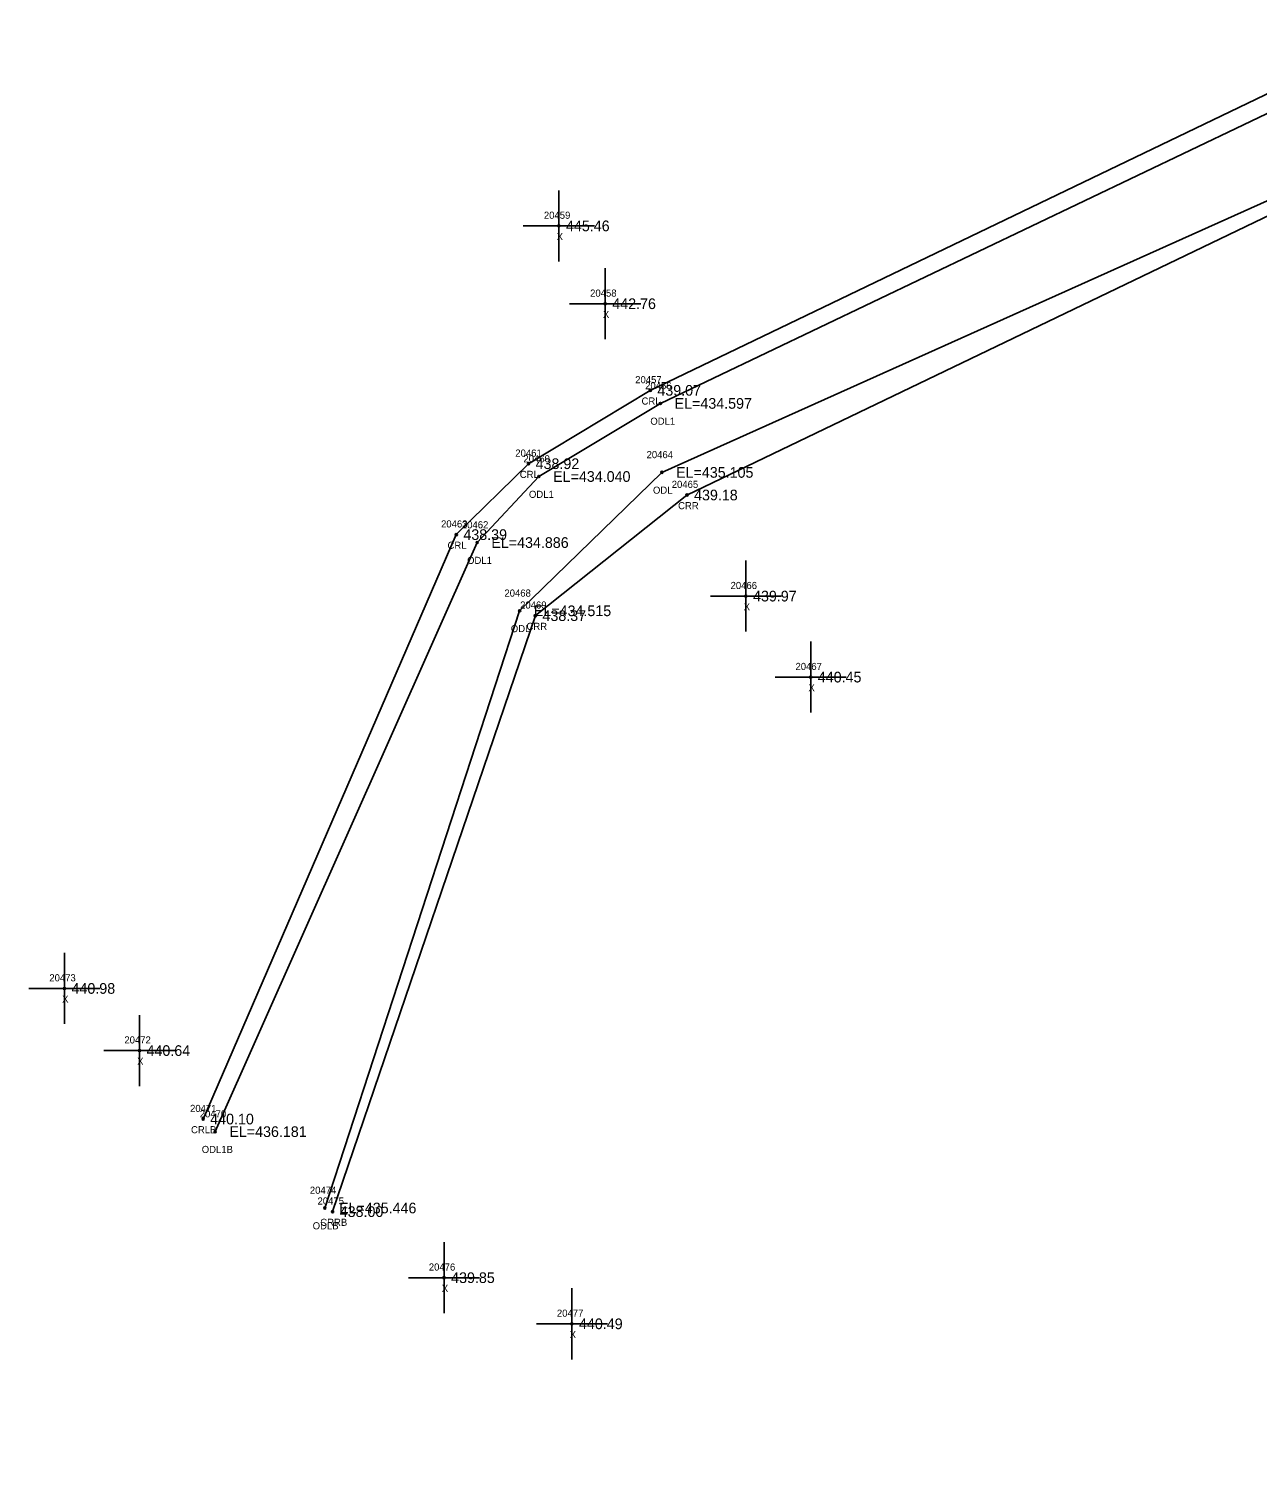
# Model space of a CAD drawing. Extents: x 1763022 to 1764007, y 824123 to 825394.
# Drawn here: x 1763021.6 to 1763194.4, y 824815.6 to 825018.5 of the extents above; entities that cross this region are included whole.
import ezdxf

# ---------------------------------------------------------------- set-up
doc = ezdxf.new("R2010")
doc.units = 0
for name, color, linetype in [('RD_EX_H2O', 7, 'Continuous'), ('RD_EX_H2O_txCode', 7, 'Continuous'), ('RD_EX_Misc', 7, 'Continuous'), ('RD_EX_Misc_txCode', 7, 'Continuous'), ('RD_EX_TX_H2O_ELEV', 7, 'Continuous'), ('RD_EX_TX_Misc_ELEV', 7, 'Continuous'), ('RD_SMD_Locator', 7, 'Continuous')]:
    doc.layers.add(name, color=color, linetype=linetype)

msp = doc.modelspace()

# ---------------------------------------------------------------- linework, layer by layer
at = {"layer": 'RD_EX_H2O'}
for points in [[(1763469.64, 824827.68), (1763444.91, 824845.55), (1763435.48, 824853.42), (1763401.74, 824907.76), (1763323.19, 824974.27), (1763226.75, 825015.18), (1763219.02, 825018.48), (1763206.39, 825014.43), (1763109.02, 824967.64), (1763091.9, 824957.32), (1763081.74, 824947.35), (1763046.14, 824865.15)], [(1763468.68, 824825.92), (1763443.51, 824843.03), (1763433.52, 824852.2), (1763400.31, 824906.96), (1763323, 824973.55), (1763227.11, 825012.29), (1763219.72, 825015.97), (1763207.36, 825012.11), (1763110.44, 824965.8), (1763093.36, 824955.52), (1763084.67, 824946.23), (1763047.83, 824863.38)], [(1763462.4, 824816.93), (1763437.96, 824834.78), (1763425.74, 824848.09), (1763393.61, 824899.16), (1763315.18, 824965.58), (1763227.67, 825003.59), (1763208.11, 824999.84), (1763110.65, 824956.1), (1763090.65, 824936.63), (1763063.26, 824852.64)], [(1763459.77, 824813.09), (1763437.3, 824833.98), (1763421.73, 824846.89), (1763391.2, 824896.67), (1763313.16, 824962.88), (1763227.9, 824997.52), (1763208.46, 824998.22), (1763114.18, 824952.92), (1763092.86, 824935.95), (1763064.35, 824852.13)]]:
    msp.add_lwpolyline(points, dxfattribs=at)
at = {"layer": 'RD_EX_Misc'}
for p, q in [((1763096.17, 824985.77), (1763096.17, 824995.77)), ((1763091.17, 824990.77), (1763101.17, 824990.77)), ((1763102.68, 824974.82), (1763102.68, 824984.82)), ((1763097.68, 824979.82), (1763107.68, 824979.82)), ((1763122.47, 824933.7), (1763122.47, 824943.7)), ((1763117.47, 824938.7), (1763127.47, 824938.7)), ((1763131.58, 824922.31), (1763131.58, 824932.31)), ((1763126.58, 824927.31), (1763136.58, 824927.31)), ((1763026.64, 824878.52), (1763026.64, 824888.52)), ((1763021.64, 824883.52), (1763031.64, 824883.52)), ((1763037.19, 824869.78), (1763037.19, 824879.78)), ((1763032.19, 824874.78), (1763042.19, 824874.78)), ((1763080.02, 824837.84), (1763080.02, 824847.84)), ((1763075.02, 824842.84), (1763085.02, 824842.84)), ((1763098, 824831.35), (1763098, 824841.35)), ((1763093, 824836.35), (1763103, 824836.35))]:
    msp.add_line(p, q, dxfattribs=at)
at = {"layer": 'RD_SMD_Locator'}
for centre in [(1763096.17, 824990.77), (1763102.68, 824979.82), (1763109.02, 824967.64), (1763110.44, 824965.8), (1763091.9, 824957.32), (1763110.65, 824956.1), (1763093.36, 824955.52), (1763114.18, 824952.92), (1763081.74, 824947.35), (1763084.67, 824946.23), (1763122.47, 824938.7), (1763090.65, 824936.63), (1763092.86, 824935.95), (1763131.58, 824927.31), (1763026.64, 824883.52), (1763037.19, 824874.78), (1763046.14, 824865.15), (1763047.83, 824863.38), (1763063.26, 824852.64), (1763064.35, 824852.13), (1763080.02, 824842.84), (1763098, 824836.35)]:
    msp.add_circle(centre, 0.15, dxfattribs=at)

# ---------------------------------------------------------------- texts
at = {"layer": 'RD_EX_H2O_txCode'}
for s, p in [('20457', (1763106.9, 824968.64)), ('20456', (1763108.3, 824967.8)), ('CRL', (1763107.79, 824965.64)), ('ODL1', (1763109.03, 824962.8)), ('20461', (1763090.04, 824958.32)), ('20460', (1763091.18, 824957.52)), ('20464', (1763108.5, 824958.1)), ('CRL', (1763090.67, 824955.32)), ('ODL', (1763109.4, 824953.1)), ('20465', (1763112.04, 824953.92)), ('ODL1', (1763091.96, 824952.52)), ('CRR', (1763112.93, 824950.92)), ('20463', (1763079.6, 824948.35)), ('20462', (1763082.53, 824948.23)), ('CRL', (1763080.51, 824945.35)), ('ODL1', (1763083.26, 824943.23)), ('20468', (1763088.51, 824938.63)), ('20469', (1763090.72, 824936.95)), ('ODL', (1763089.41, 824933.63)), ('CRR', (1763091.61, 824933.95)), ('20471', (1763044.31, 824866.15)), ('20470', (1763045.67, 824865.38)), ('CRLB', (1763044.44, 824863.15)), ('ODL1B', (1763045.95, 824860.38)), ('20474', (1763061.15, 824854.64)), ('20475', (1763062.23, 824853.13)), ('ODLB', (1763061.55, 824849.64)), ('CRRB', (1763062.62, 824850.13))]:
    msp.add_text(s, height=1, dxfattribs=at).set_placement(p)
at = {"layer": 'RD_EX_Misc_txCode'}
for s, p in [('20459', (1763094.06, 824991.77)), ('X', (1763095.86, 824988.77)), ('20458', (1763100.56, 824980.82)), ('X', (1763102.36, 824977.82)), ('20466', (1763120.31, 824939.7)), ('X', (1763122.16, 824936.7)), ('20467', (1763129.44, 824928.31)), ('X', (1763131.27, 824925.31)), ('20473', (1763024.52, 824884.52)), ('X', (1763026.32, 824881.52)), ('20472', (1763035.07, 824875.78)), ('X', (1763036.87, 824872.78)), ('20476', (1763077.88, 824843.84)), ('X', (1763079.71, 824840.84)), ('20477', (1763095.89, 824837.35)), ('X', (1763097.69, 824834.35))]:
    msp.add_text(s, height=1, dxfattribs=at).set_placement(p)
at = {"layer": 'RD_EX_TX_H2O_ELEV'}
for s, p in [('439.07', (1763110.02, 824966.89)), ('EL=434.597', (1763112.44, 824965.05)), ('438.92', (1763092.9, 824956.57)), ('EL=434.040', (1763095.36, 824954.77)), ('EL=435.105', (1763112.65, 824955.35)), ('439.18', (1763115.18, 824952.17)), ('438.39', (1763082.74, 824946.6)), ('EL=434.886', (1763086.67, 824945.48)), ('EL=434.515', (1763092.65, 824935.88)), ('438.37', (1763093.86, 824935.2)), ('440.10', (1763047.14, 824864.4)), ('EL=436.181', (1763049.83, 824862.63)), ('438.00', (1763065.35, 824851.38)), ('EL=435.446', (1763065.26, 824851.89))]:
    msp.add_text(s, height=1.5, dxfattribs=at).set_placement(p)
at = {"layer": 'RD_EX_TX_Misc_ELEV'}
for s, p in [('445.46', (1763097.17, 824990.02)), ('442.76', (1763103.68, 824979.07)), ('439.97', (1763123.47, 824937.95)), ('440.45', (1763132.58, 824926.56)), ('440.98', (1763027.64, 824882.77)), ('440.64', (1763038.19, 824874.03)), ('439.85', (1763081.02, 824842.09)), ('440.49', (1763099, 824835.6))]:
    msp.add_text(s, height=1.5, dxfattribs=at).set_placement(p)

doc.saveas('drawing.dxf')
